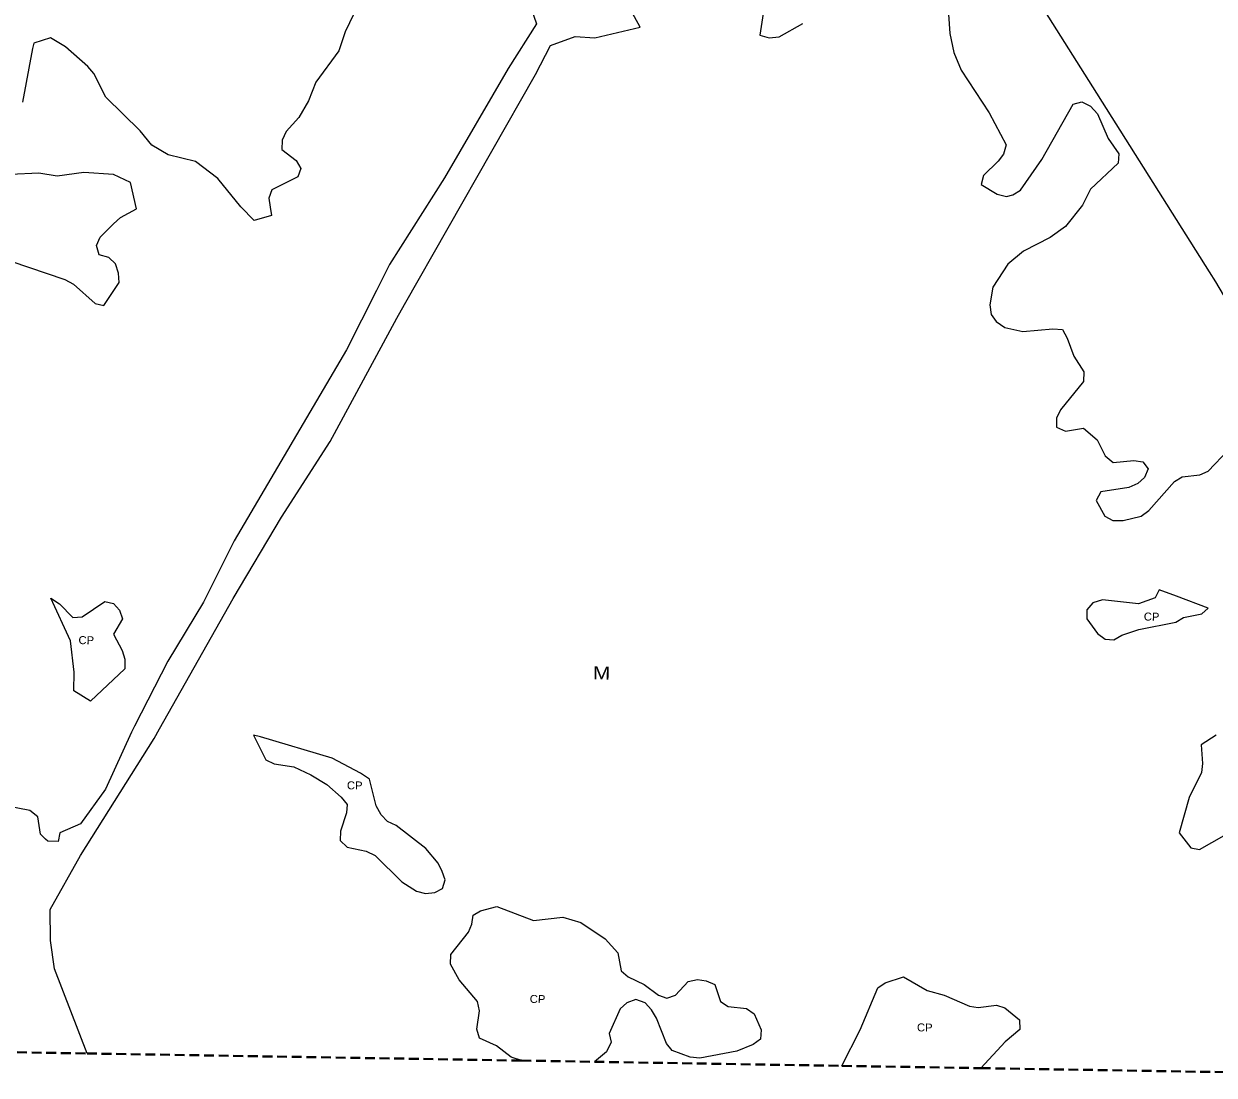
# Model space of a CAD drawing. Extents: x 713589 to 726391, y 7177764 to 7191819.
# Drawn here: x 718159 to 719111, y 7177879 to 7178720 of the extents above; entities that cross this region are included whole.
import ezdxf
from ezdxf.enums import TextEntityAlignment as Align

# ---------------------------------------------------------------- set-up
doc = ezdxf.new("R2010")
doc.units = 0
doc.header["$LTSCALE"] = 2.6
doc.linetypes.add('MEDIUM_DASHED', pattern=[4.5, 3, -1.5])
doc.layers.add('63', color=7, linetype='Continuous', lineweight=25)

msp = doc.modelspace()

# ---------------------------------------------------------------- linework, layer by layer
at = {"layer": '63'}
for points in [[(718838.82, 7179163.06), (718828.12, 7179158.53), (718794.44, 7179144.27), (718739.17, 7179106.93), (718770.73, 7179057.83), (718801.73, 7179009.6), (718825.05, 7178971.22), (718875.74, 7178887.82), (718880.38, 7178880.19), (718880.89, 7178879.35), (718890.45, 7178864.16), (718971.65, 7178735.2), (719013.14, 7178669.3), (719106.43, 7178521.14), (719111.47, 7178513.14), (719136.8, 7178470.37), (719165.62, 7178428.86), (719189.56, 7178386.56), (719224.52, 7178313.68)], [(718209.32, 7177895.98), (718183.33, 7177963.74), (718180.04, 7177986.45), (718179.8, 7178011.18), (718204.1, 7178054.27), (718263.04, 7178148.03), (718267.4, 7178155.76), (718326.1, 7178259.85), (718364.76, 7178325.1), (718403.74, 7178385.6), (718456.97, 7178484.11), (718463.29, 7178495.23), (718567.89, 7178679.23), (718579.76, 7178702.42), (718599.57, 7178709.64), (718615.41, 7178708.37), (718651.52, 7178716.92), (718641.07, 7178735.93)], [(718425.97, 7178734.38), (718415.83, 7178713.16), (718410.76, 7178697.95), (718392.38, 7178672.93), (718386.36, 7178658.04), (718378.76, 7178644.74), (718368.62, 7178633.65), (718365.45, 7178626.68), (718365.13, 7178619.08), (718376.53, 7178610.21), (718380.33, 7178603.87), (718377.8, 7178597.22), (718357.2, 7178586.77), (718354.67, 7178580.11), (718355.82, 7178572.98), (718356.9, 7178566.31), (718342.94, 7178562.38), (718332.18, 7178573.15), (718313.81, 7178595.96), (718296.07, 7178609.59), (718274.21, 7178614.98), (718261.22, 7178622.58), (718251.72, 7178633.99), (718224.48, 7178660.92), (718214.67, 7178679.93), (718209.91, 7178685.63)], [(718897.67, 7178735.25), (718899.25, 7178711.8), (718902.42, 7178696.6), (718908.12, 7178682.66), (718930.6, 7178648.44), (718944.22, 7178622.78), (718942, 7178615.49), (718937.88, 7178609.79), (718926.16, 7178598.39), (718924.26, 7178591.1), (718936.93, 7178583.5), (718944.53, 7178581.6), (718949.47, 7178582.94), (718955.62, 7178586.66), (718972.73, 7178611.05), (718997.76, 7178655.4), (719004.73, 7178657.3), (719011.7, 7178653.81), (719017.09, 7178647.79), (719025.64, 7178627.83), (719034.19, 7178615.79), (719033.87, 7178608.19), (719011.69, 7178587.29), (719005.35, 7178574.62), (718991.73, 7178557.51), (718979.37, 7178548.64), (718958.14, 7178537.88), (718945.47, 7178527.42), (718933.43, 7178509.05), (718931.21, 7178494.8), (718932.16, 7178487.19), (718936.28, 7178481.49), (718943.25, 7178476.74), (718957.5, 7178473.57), (718981.58, 7178475.78), (718989.18, 7178475.15), (718992.98, 7178468.18)], [(718564.41, 7178731.82), (718568.66, 7178719.67), (718546.03, 7178683.99), (718495.01, 7178596.56), (718451.28, 7178527.19), (718440.69, 7178506.21), (718416.74, 7178458.77), (718327.06, 7178306.1), (718302.34, 7178257), (718273.82, 7178209.8), (718247.42, 7178157.9), (718244.98, 7178153.1), (718224.07, 7178107.49), (718204.11, 7178079.61), (718187.61, 7178072.4), (718186.3, 7178065.67), (718177.88, 7178065.7), (718176.18, 7178067.4), (718172.18, 7178071.4), (718169.96, 7178085.34), (718163.63, 7178090.41), (718143.04, 7178094.22)], [(718750.37, 7178731.47), (718747.19, 7178710.56), (718754.8, 7178708.34), (718762.72, 7178709.29), (718781.73, 7178720.06)], [(718209.91, 7178685.63), (718192.18, 7178701.16), (718180.14, 7178708.45), (718166.79, 7178704.07), (718165.69, 7178699.88), (718157.78, 7178657.1)], [(718148.32, 7178529.79), (718191.51, 7178515.2), (718198.48, 7178511.4), (718215.9, 7178495.87), (718222.87, 7178494.29), (718234.91, 7178512.66), (718234.59, 7178520.26), (718232.06, 7178527.55), (718226.68, 7178532.62), (718219.07, 7178534.84), (718216.86, 7178542.44), (718219.71, 7178549.09), (718230.48, 7178559.55), (718236.19, 7178564.61), (718248.86, 7178571.58), (718244.11, 7178592.81), (718230.49, 7178599.14), (718206.73, 7178600.73), (718185.51, 7178597.88), (718170.93, 7178600.1), (718148.09, 7178599.14)], [(718992.98, 7178468.18), (718998.36, 7178453.92), (719006.28, 7178441.25), (719005.96, 7178433.64), (718987.58, 7178410.84), (718984.42, 7178404.19), (718984.41, 7178396.9), (718991.7, 7178393.73), (719005.96, 7178396.26), (719017.04, 7178386.76), (719023.37, 7178374.08), (719029.71, 7178368.7), (719046.18, 7178370.28), (719053.47, 7178369.33), (719057.59, 7178363.62), (719054.73, 7178356.66), (719049.35, 7178351.9), (719042.38, 7178348.74), (719019.89, 7178345.26), (719016.08, 7178338.29), (719023.05, 7178325.93), (719029.38, 7178322.45), (719037.62, 7178322.45), (719052.19, 7178325.93), (719058.21, 7178330.36), (719078.81, 7178353.48), (719084.83, 7178357.28), (719099.08, 7178358.87), (719105.74, 7178361.71), (719121.9, 7178378.82)], [(719112.04, 7178150.73), (719100, 7178142.81), (719101.26, 7178127.93), (719100.31, 7178120.64), (719090.49, 7178100.68), (719082.56, 7178072.49), (719091.75, 7178060.45), (719098.72, 7178059.18), (719130.08, 7178076.92)], [(718556.67, 7177890.27), (718548.42, 7177892.96), (718536.7, 7177902.15), (718523.08, 7177908.17), (718520.87, 7177915.46), (718523.09, 7177930.03), (718521.5, 7177937.64), (718506.93, 7177954.75), (718499.97, 7177967.42), (718500.29, 7177975.02), (718514.23, 7177993.08), (718517.08, 7177999.41), (718518.03, 7178006.7), (718524.05, 7178010.18), (718536.88, 7178013.55), (718566.18, 7178002.25), (718589.63, 7178005.1), (718604.2, 7178000.66), (718623.52, 7177987.67), (718633.65, 7177976.58), (718636.5, 7177962.01), (718641.89, 7177957.26), (718654.87, 7177951.24), (718666.28, 7177942.68), (718672.93, 7177940.14), (718679.9, 7177942.68), (718690.04, 7177953.45), (718697.32, 7177955.03), (718704.29, 7177954.08), (718711.26, 7177951.23), (718715.7, 7177937.6), (718722.03, 7177933.48), (718736.6, 7177931.9), (718742.62, 7177927.78), (718748.32, 7177914.79), (718747.69, 7177907.5), (718741.98, 7177903.07), (718728.99, 7177897.68), (718699.21, 7177892.3), (718691.61, 7177892.94), (718677.04, 7177898.33), (718672.61, 7177904.03), (718664.69, 7177924.31), (718660.57, 7177930.96), (718655.51, 7177936.35), (718648.22, 7177939.2), (718640.93, 7177936.35), (718635.55, 7177931.6), (718626.67, 7177911.96), (718628.26, 7177904.99), (718624.77, 7177897.39), (718615.05, 7177889.31)], [(718812.92, 7177886.06), (718827.52, 7177914.77), (718841.46, 7177948.35), (718847.48, 7177952.47), (718862.06, 7177957.22), (718881.06, 7177946.44), (718894.68, 7177942.64), (718914.96, 7177933.77), (718921.92, 7177932.81), (718936.5, 7177934.71), (718943.15, 7177932.49), (718954.87, 7177922.99), (718955.18, 7177915.07), (718943.46, 7177905.25), (718923.9, 7177884.23)]]:
    msp.add_lwpolyline(points, dxfattribs=at)
for points in [[(718230.43, 7178231.35), (718237.39, 7178218.36), (718239.61, 7178211.39), (718239.61, 7178203.79), (718212.22, 7178177.89), (718198.9, 7178186.1), (718199.17, 7178201), (718196.21, 7178225.97), (718180.47, 7178260.32), (718187.35, 7178255.75), (718198.12, 7178244.66), (718205.4, 7178245.29), (718223.46, 7178257.65), (718230.43, 7178256.06), (718235.18, 7178250.67), (718237.71, 7178243.71)], [(719030.32, 7178226.78), (719036.65, 7178230.58), (719050.28, 7178235.01), (719079.74, 7178241.02), (719086.08, 7178244.82), (719100.65, 7178247.67), (719105.69, 7178252.19), (719080.47, 7178261.78), (719066.43, 7178266.82), (719063.27, 7178260.35), (719049.96, 7178255.6), (719021.14, 7178258.77), (719013.53, 7178256.56), (719008.78, 7178250.86), (719008.78, 7178243.57), (719017.33, 7178231.85), (719023.35, 7178227.41)], [(718480.02, 7178023.81), (718487.31, 7178024.76), (718493.64, 7178027.93), (718495.54, 7178034.9), (718493.33, 7178041.55), (718490.16, 7178048.2), (718480.34, 7178059.92), (718456.59, 7178078.3), (718449.62, 7178081.47), (718444.55, 7178086.86), (718440.43, 7178094.14), (718435.22, 7178115.51), (718428.08, 7178120.12), (718405.28, 7178132.17), (718347.94, 7178149.28), (718342.42, 7178150.57), (718352.37, 7178130.91), (718359.02, 7178127.74), (718374.55, 7178125.2), (718388.17, 7178118.86), (718401.15, 7178111.26), (718412.56, 7178101.12), (718417.31, 7178095.1), (718416.67, 7178088.45), (718411.92, 7178073.88), (718411.6, 7178066.27), (718417.3, 7178060.89), (718432.51, 7178057.72), (718439.79, 7178054.23), (718461.01, 7178033.32), (718472.73, 7178025.71)]]:
    msp.add_lwpolyline(points, close=True, dxfattribs=at)
at = {"layer": '63', "linetype": 'MEDIUM_DASHED', "lineweight": 40}
for points in [[(718106.6, 7177897.67), (718209.32, 7177895.98), (718556.67, 7177890.27)], [(718556.67, 7177890.27), (718615.05, 7177889.31), (718812.92, 7177886.06), (718923.9, 7177884.23)], [(718923.9, 7177884.23), (719250.63, 7177878.86), (719267.44, 7177878.58)]]:
    msp.add_lwpolyline(points, dxfattribs=at)

# ---------------------------------------------------------------- texts
at = {"layer": '63'}
for s, height, width, p in [('CP', 6.4, 1.05, (719060.44, 7178242.22)), ('CP', 6.4, 1.05, (718208.71, 7178223.38)), ('M', 10.4, 1.2, (718620.65, 7178195.17)), ('CP', 6.4, 1.05, (718423.33, 7178107.21)), ('CP', 6.4, 1.05, (718569.51, 7177936.33)), ('CP', 6.4, 1.05, (718879.07, 7177913.57))]:
    msp.add_text(s, height=height, rotation=359.062, dxfattribs=dict(at, width=width)).set_placement(p, align=Align.CENTER)

doc.saveas('drawing.dxf')
